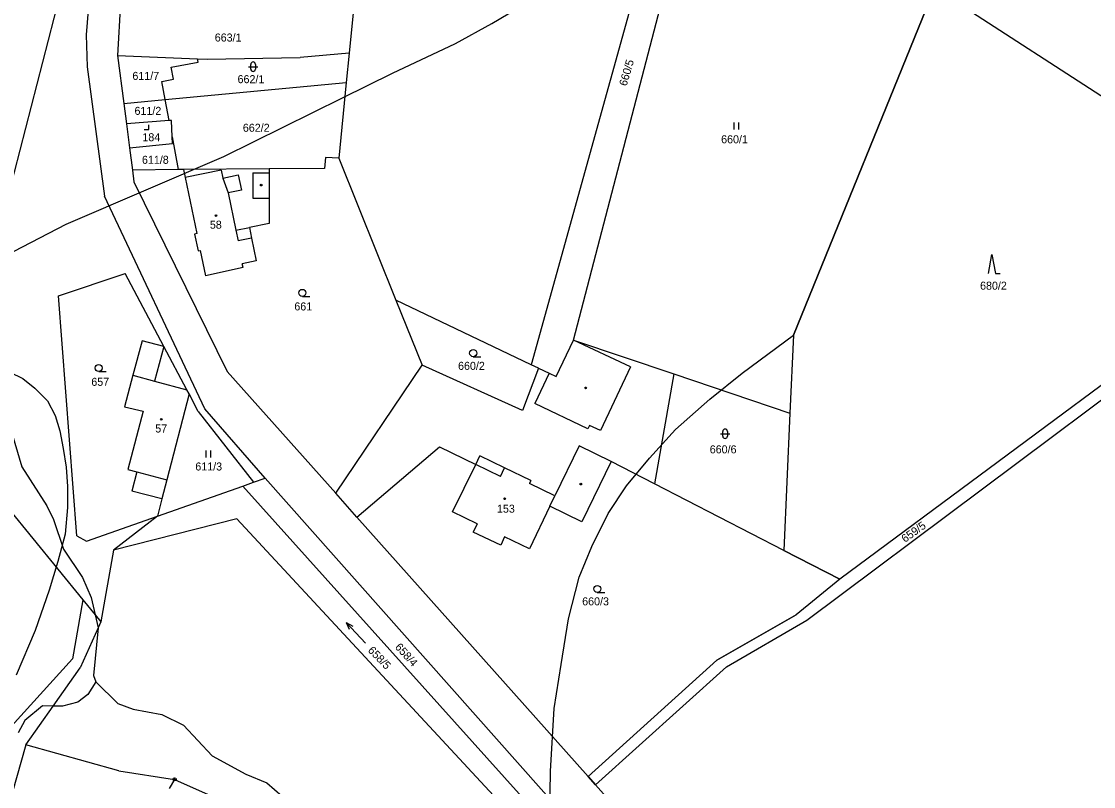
# Model space of a CAD drawing. Extents: x -546762 to -540209, y -1046851 to -1035694.
# Drawn here: x -544180.8 to -543953, y -1042590.2 to -1042427.6 of the extents above; entities that cross this region are included whole.
import ezdxf

# ---------------------------------------------------------------- set-up
doc = ezdxf.new("R2010")
doc.units = 0
for name, color, linetype in [('Vrstva 1', 7, 'Continuous'), ('Vrstva 18', 7, 'Continuous'), ('Vrstva 19', 7, 'Continuous'), ('Vrstva 24', 7, 'Continuous'), ('Vrstva 25', 7, 'Continuous'), ('Vrstva 3', 7, 'Continuous'), ('Vrstva 37', 7, 'Continuous'), ('Vrstva 4', 7, 'Continuous'), ('Vrstva 52', 7, 'Continuous')]:
    doc.layers.add(name, color=color, linetype=linetype)

msp = doc.modelspace()

# ---------------------------------------------------------------- linework, layer by layer
at = {"layer": 'Vrstva 1'}
msp.add_line((-543914, -1042467.7), (-543986.75, -1042420.55), dxfattribs=at)
for points in [[(-544038.85, -1042379.66), (-544072.43, -1042500.56)], [(-544063.47, -1042495.3), (-544034.28, -1042383.4)], [(-544164.15, -1042395.46), (-544167.03, -1042430.46)], [(-544107.72, -1042399.99), (-544111.16, -1042434.37)], [(-544169.04, -1042408.16), (-544185.97, -1042473.64)], [(-544016.72, -1042494.3), (-543986.75, -1042420.55)], [(-544159.71, -1042423.65), (-544160.33, -1042434.89)], [(-544167.03, -1042430.46), (-544166.81, -1042437.26)], [(-544160.33, -1042434.89), (-544143.34, -1042435.58)], [(-544160.33, -1042434.89), (-544159.01, -1042445.05)], [(-544148.97, -1042437.33), (-544143.21, -1042436.27)], [(-544143.34, -1042435.58), (-544141.33, -1042435.66)], [(-544143.21, -1042436.27), (-544143.34, -1042435.58)], [(-544141.33, -1042435.66), (-544121.51, -1042435.3)], [(-544111.16, -1042434.37), (-544121.51, -1042435.3)], [(-544111.16, -1042434.37), (-544111.76, -1042440.57)], [(-544166.81, -1042437.26), (-544163.09, -1042464.73)], [(-544148.49, -1042439.92), (-544148.97, -1042437.33)], [(-544150.91, -1042440.37), (-544148.49, -1042439.92)], [(-544150.2, -1042444.21), (-544150.91, -1042440.37)], [(-544150.2, -1042444.21), (-544111.76, -1042440.57)], [(-544111.76, -1042440.57), (-544113.33, -1042456.67)], [(-544159.01, -1042445.05), (-544150.2, -1042444.21)], [(-544159.01, -1042445.05), (-544158.45, -1042449.39)], [(-544149.38, -1042448.68), (-544150.2, -1042444.21)], [(-544149.38, -1042448.68), (-544158.45, -1042449.39)], [(-544158.45, -1042449.39), (-544157.79, -1042454.48)], [(-544148.9, -1042448.64), (-544149.38, -1042448.68)], [(-544148.73, -1042452.17), (-544148.9, -1042448.64)], [(-544148.66, -1042453.58), (-544148.73, -1042452.17)], [(-544148.73, -1042452.17), (-544147.44, -1042459.11)], [(-544157.79, -1042454.48), (-544148.66, -1042453.58)], [(-544157.79, -1042454.48), (-544157.18, -1042459.2)], [(-544116.18, -1042456.56), (-544116.37, -1042458.83)], [(-544113.33, -1042456.67), (-544116.18, -1042456.56)], [(-544113.33, -1042456.67), (-544101.21, -1042486.85)], [(-544147.44, -1042459.11), (-544157.18, -1042459.2)], [(-544146.34, -1042459.1), (-544147.44, -1042459.11)], [(-544128.11, -1042458.94), (-544146.34, -1042459.1)], [(-544146.34, -1042459.1), (-544145.99, -1042460.8)], [(-544128.11, -1042458.94), (-544128.12, -1042459.8)], [(-544116.37, -1042458.83), (-544128.11, -1042458.94)], [(-544157.18, -1042459.2), (-544156.86, -1042461.7)], [(-544145.99, -1042460.8), (-544143.52, -1042472.69)], [(-544128.12, -1042459.8), (-544128.13, -1042465.15)], [(-544156.86, -1042461.7), (-544137.04, -1042501.98)], [(-544141.77, -1042509.92), (-544163.09, -1042464.73)], [(-544128.13, -1042465.15), (-544128.16, -1042470.53)], [(-544128.16, -1042470.53), (-544132.34, -1042471.39)], [(-544143.52, -1042472.69), (-544143.96, -1042472.79)], [(-544143.96, -1042472.79), (-544143.23, -1042476.36)], [(-544132.34, -1042471.39), (-544131.87, -1042473.64)], [(-544131.87, -1042473.64), (-544130.88, -1042478.49)], [(-544143.23, -1042476.36), (-544142.8, -1042476.29)], [(-544142.8, -1042476.29), (-544141.65, -1042481.64)], [(-544130.88, -1042478.49), (-544133.85, -1042479.1)], [(-544133.68, -1042479.87), (-544133.85, -1042479.1)], [(-544172.9, -1042485.9), (-544158.73, -1042481.16)], [(-544150.51, -1042496.7), (-544158.73, -1042481.16)], [(-544133.68, -1042479.87), (-544141.65, -1042481.64)], [(-544169, -1042536.88), (-544172.9, -1042485.9)], [(-544101.21, -1042486.85), (-544095.65, -1042500.68)], [(-544072.43, -1042500.56), (-544101.21, -1042486.85)], [(-544155.14, -1042495.45), (-544157.11, -1042502.79)], [(-544150.51, -1042496.7), (-544155.14, -1042495.45)], [(-544067.15, -1042503.08), (-544063.47, -1042495.3)], [(-544063.47, -1042495.3), (-544042.15, -1042502.5)], [(-544016.72, -1042494.3), (-544017.46, -1042510.83)], [(-544145.65, -1042505.87), (-544150.51, -1042496.7)], [(-543939.58, -1042496.26), (-544006.86, -1042546.1)], [(-544013.86, -1042554.81), (-543939.22, -1042499.03)], [(-544113.99, -1042527.84), (-544137.04, -1042501.98)], [(-544113.99, -1042527.84), (-544095.65, -1042500.68)], [(-544074.29, -1042510.25), (-544095.65, -1042500.68)], [(-544070.87, -1042501.31), (-544074.29, -1042510.25)], [(-544070.87, -1042501.31), (-544072.43, -1042500.56)], [(-544070.87, -1042501.31), (-544068.64, -1042502.37)], [(-544068.64, -1042502.37), (-544067.15, -1042503.08)], [(-544157.11, -1042502.79), (-544158.87, -1042509.49)], [(-544042.15, -1042502.5), (-544046.28, -1042525.83)], [(-544042.15, -1042502.5), (-544017.46, -1042510.83)], [(-544145.11, -1042506.77), (-544149.87, -1042524.97)], [(-544145.11, -1042506.77), (-544145.65, -1042505.87)], [(-544143.21, -1042510.47), (-544145.11, -1042506.77)], [(-544158.87, -1042509.49), (-544154.9, -1042510.41)], [(-544154.9, -1042510.41), (-544158.13, -1042522.84)], [(-544143.21, -1042510.47), (-544131.43, -1042525.51)], [(-544128.99, -1042524.65), (-544141.77, -1042509.92)], [(-544017.46, -1042510.83), (-544018.75, -1042539.99)], [(-544109.47, -1042532.91), (-544091.91, -1042518.02)], [(-544091.91, -1042518.02), (-544084.22, -1042521.74)], [(-544158.13, -1042522.84), (-544156.25, -1042523.32)], [(-544089.17, -1042531.78), (-544084.22, -1042521.74)], [(-544055.43, -1042521.13), (-544061.66, -1042533.93)], [(-544046.28, -1042525.83), (-544055.43, -1042521.13)], [(-544156.25, -1042523.32), (-544157.31, -1042527.4)], [(-544149.87, -1042524.97), (-544150.92, -1042529.06)], [(-544131.43, -1042525.51), (-544128.99, -1042524.65)], [(-544055.22, -1042607.7), (-544128.99, -1042524.65)], [(-544150.92, -1042529.06), (-544157.31, -1042527.4)], [(-544151.86, -1042532.7), (-544133.73, -1042526.32)], [(-544133.73, -1042526.32), (-544131.43, -1042525.51)], [(-544133.73, -1042526.32), (-544057.53, -1042611.21)], [(-544018.75, -1042539.99), (-544046.28, -1042525.83)], [(-544150.92, -1042529.06), (-544151.86, -1042532.7)], [(-544109.47, -1042532.91), (-544113.99, -1042527.84)], [(-544183.66, -1042530.96), (-544167.74, -1042550.47)], [(-544083.92, -1042534.32), (-544089.17, -1042531.78)], [(-544068.48, -1042530.61), (-544072.84, -1042539.65)], [(-544061.66, -1042533.93), (-544068.48, -1042530.61)], [(-544166.94, -1042538), (-544151.86, -1042532.7)], [(-544151.86, -1042532.7), (-544161.24, -1042539.94)], [(-544135.03, -1042533.32), (-544161.24, -1042539.94)], [(-544064.09, -1042609.7), (-544135.03, -1042533.32)], [(-544060.37, -1042588.02), (-544109.47, -1042532.91)], [(-544083.92, -1042534.32), (-544084.75, -1042536.12)], [(-544078.92, -1042538.91), (-544084.75, -1042536.12)], [(-544169, -1042536.88), (-544166.94, -1042538)], [(-544078.09, -1042537.11), (-544078.92, -1042538.91)], [(-544072.84, -1042539.65), (-544078.09, -1042537.11)], [(-544161.24, -1042539.94), (-544163.9, -1042555.17)], [(-544006.86, -1042546.1), (-544018.75, -1042539.99)], [(-544006.86, -1042546.1), (-544016.14, -1042553.71)], [(-544167.74, -1042550.47), (-544169.9, -1042563.04)], [(-544167.74, -1042550.47), (-544165.08, -1042553.72)], [(-544165.08, -1042553.72), (-544163.9, -1042555.17)], [(-544032.97, -1042563.33), (-544016.14, -1042553.71)], [(-544030.98, -1042564.71), (-544013.86, -1042554.81)], [(-544164.47, -1042556.43), (-544168.31, -1042564.91)], [(-544163.9, -1042555.17), (-544164.47, -1042556.43)], [(-544185.03, -1042579.7), (-544169.9, -1042563.04)], [(-544032.97, -1042563.33), (-544060.37, -1042588.02)], [(-544174.05, -1042573.07), (-544168.31, -1042564.91)], [(-544030.98, -1042564.71), (-544058.8, -1042589.78)], [(-544179.83, -1042581.29), (-544174.05, -1042573.07)], [(-544179.83, -1042581.29), (-544188.45, -1042611.64)], [(-544160.08, -1042586.86), (-544179.83, -1042581.29)], [(-544160.08, -1042586.86), (-544148.22, -1042588.65)], [(-544148.22, -1042588.65), (-544149.36, -1042590.55)], [(-544148.22, -1042588.65), (-544135.96, -1042594.1)], [(-544058.8, -1042589.78), (-544060.37, -1042588.02)], [(-543992.15, -1042664.59), (-544058.8, -1042589.78)]]:
    msp.add_lwpolyline(points, dxfattribs=at)
at = {"layer": 'Vrstva 24'}
for radius in [0.335, 0.067]:
    msp.add_circle((-544148.22, -1042588.65), radius, dxfattribs=at)
at = {"layer": 'Vrstva 25'}
for p, q in [((-544132.55, -1042437.24), (-544130.55, -1042437.24)), ((-544132.05, -1042437.74), (-544132.05, -1042436.74)), ((-544131.05, -1042436.74), (-544131.05, -1042437.74)), ((-544029.35, -1042450.59), (-544029.35, -1042449.09)), ((-544028.35, -1042450.59), (-544028.35, -1042449.09)), ((-544121.08, -1042486.04), (-544119.48, -1042486.04)), ((-544084.78, -1042498.84), (-544083.18, -1042498.84)), ((-544164.35, -1042501.99), (-544162.75, -1042501.99)), ((-544032.26, -1042515.22), (-544030.26, -1042515.22)), ((-544031.76, -1042515.72), (-544031.76, -1042514.72)), ((-544030.76, -1042514.72), (-544030.76, -1042515.72)), ((-544141.52, -1042520.28), (-544141.52, -1042518.78)), ((-544140.52, -1042520.28), (-544140.52, -1042518.78)), ((-544058.41, -1042548.93), (-544056.81, -1042548.93))]:
    msp.add_line(p, q, dxfattribs=at)
for points in [[(-544154.7, -1042450.58), (-544153.7, -1042450.58), (-544153.7, -1042449.58)], [(-543975.28, -1042481.14), (-543974.58, -1042477.14), (-543973.78, -1042481.14), (-543972.78, -1042481.14)], [(-544107.64, -1042559.67), (-544111.78, -1042555.33), (-544111.11, -1042556.76)], [(-544111.78, -1042555.33), (-544110.38, -1042556.07)]]:
    msp.add_lwpolyline(points, dxfattribs=at)
for centre, radius in [((-544129.82, -1042462.4), 0.175), ((-544139.42, -1042468.86), 0.175), ((-544121.08, -1042485.29), 0.75), ((-544084.78, -1042498.09), 0.75), ((-544164.35, -1042501.24), 0.75), ((-544060.89, -1042505.47), 0.175), ((-544151.06, -1042512.14), 0.175), ((-544061.91, -1042525.91), 0.175), ((-544078.1, -1042529.03), 0.175), ((-544058.41, -1042548.18), 0.75)]:
    msp.add_circle(centre, radius, dxfattribs=at)
for centre, start, end in [((-544131.55, -1042436.74), 0, 180), ((-544131.55, -1042437.74), 180, 0), ((-544031.26, -1042514.72), 0, 180), ((-544031.26, -1042515.72), 180, 0)]:
    msp.add_arc(centre, 0.5, start, end, dxfattribs=at)
at = {"layer": 'Vrstva 3'}
for points in [[(-544138.34, -1042459.2), (-544145.99, -1042460.8)], [(-544145.99, -1042460.8), (-544143.52, -1042472.69)], [(-544138.34, -1042459.2), (-544137.98, -1042460.91)], [(-544137.98, -1042460.91), (-544136.82, -1042464.04)], [(-544136.82, -1042464.04), (-544135.18, -1042471.97)], [(-544143.52, -1042472.69), (-544143.96, -1042472.79)], [(-544143.96, -1042472.79), (-544143.23, -1042476.36)], [(-544135.18, -1042471.97), (-544134.71, -1042474.22)], [(-544131.87, -1042473.64), (-544134.71, -1042474.22)], [(-544131.87, -1042473.64), (-544130.88, -1042478.49)], [(-544143.23, -1042476.36), (-544142.8, -1042476.29)], [(-544142.8, -1042476.29), (-544141.65, -1042481.64)], [(-544130.88, -1042478.49), (-544133.85, -1042479.1)], [(-544133.68, -1042479.87), (-544133.85, -1042479.1)], [(-544133.68, -1042479.87), (-544141.65, -1042481.64)], [(-544157.11, -1042502.79), (-544158.87, -1042509.49)], [(-544157.11, -1042502.79), (-544152.48, -1042504.03)], [(-544152.48, -1042504.03), (-544145.65, -1042505.87)], [(-544145.11, -1042506.77), (-544149.87, -1042524.97)], [(-544145.11, -1042506.77), (-544145.65, -1042505.87)], [(-544158.87, -1042509.49), (-544154.9, -1042510.41)], [(-544154.9, -1042510.41), (-544158.13, -1042522.84)], [(-544158.13, -1042522.84), (-544156.25, -1042523.32)], [(-544089.17, -1042531.78), (-544084.22, -1042521.74)], [(-544078.97, -1042524.28), (-544084.22, -1042521.74)], [(-544078.97, -1042524.28), (-544078.13, -1042522.47)], [(-544072.52, -1042525.17), (-544078.13, -1042522.47)], [(-544156.25, -1042523.32), (-544149.87, -1042524.97)], [(-544072.52, -1042525.17), (-544072.82, -1042525.79)], [(-544067.42, -1042528.42), (-544072.82, -1042525.79)], [(-544068.48, -1042530.61), (-544067.42, -1042528.42)], [(-544083.92, -1042534.32), (-544089.17, -1042531.78)], [(-544068.48, -1042530.61), (-544072.84, -1042539.65)], [(-544083.92, -1042534.32), (-544084.75, -1042536.12)], [(-544078.92, -1042538.91), (-544084.75, -1042536.12)], [(-544078.09, -1042537.11), (-544078.92, -1042538.91)], [(-544072.84, -1042539.65), (-544078.09, -1042537.11)]]:
    msp.add_lwpolyline(points, dxfattribs=at)
at = {"layer": 'Vrstva 37'}
for centre in [(-544139.42, -1042468.86), (-544151.06, -1042512.14), (-544078.1, -1042529.03)]:
    msp.add_circle(centre, 0.175, dxfattribs=at)
at = {"layer": 'Vrstva 4'}
for points in [[(-544138.34, -1042459.2), (-544145.99, -1042460.8)], [(-544138.34, -1042459.2), (-544137.98, -1042460.91)], [(-544137.98, -1042460.91), (-544134.7, -1042460.23)], [(-544137.98, -1042460.91), (-544136.82, -1042464.04)], [(-544134.7, -1042460.23), (-544134.03, -1042463.46)], [(-544131.62, -1042459.79), (-544131.63, -1042465.14)], [(-544131.62, -1042459.79), (-544128.12, -1042459.8)], [(-544134.03, -1042463.46), (-544136.82, -1042464.04)], [(-544136.82, -1042464.04), (-544135.18, -1042471.97)], [(-544131.63, -1042465.14), (-544128.13, -1042465.15)], [(-544135.18, -1042471.97), (-544132.34, -1042471.39)], [(-544135.18, -1042471.97), (-544134.71, -1042474.22)], [(-544131.87, -1042473.64), (-544134.71, -1042474.22)], [(-544051.35, -1042501.03), (-544063.47, -1042495.3)], [(-544150.51, -1042496.7), (-544152.48, -1042504.03)], [(-544068.64, -1042502.37), (-544071.67, -1042508.77)], [(-544051.35, -1042501.03), (-544057.74, -1042514.54)], [(-544157.11, -1042502.79), (-544152.48, -1042504.03)], [(-544152.48, -1042504.03), (-544145.65, -1042505.87)], [(-544060.43, -1042514.16), (-544071.67, -1042508.77)], [(-544060.08, -1042513.43), (-544060.43, -1042514.16)], [(-544057.74, -1042514.54), (-544060.08, -1042513.43)], [(-544183.1, -1042514.08), (-544180.67, -1042522.21)], [(-544062.26, -1042517.81), (-544067.42, -1042528.42)], [(-544055.43, -1042521.13), (-544062.26, -1042517.81)], [(-544084.22, -1042521.74), (-544083.39, -1042519.94)], [(-544078.13, -1042522.47), (-544083.39, -1042519.94)], [(-544180.67, -1042522.21), (-544175.39, -1042530.5)], [(-544078.97, -1042524.28), (-544084.22, -1042521.74)], [(-544078.97, -1042524.28), (-544078.13, -1042522.47)], [(-544072.52, -1042525.17), (-544078.13, -1042522.47)], [(-544156.25, -1042523.32), (-544149.87, -1042524.97)], [(-544072.52, -1042525.17), (-544072.82, -1042525.79)], [(-544067.42, -1042528.42), (-544072.82, -1042525.79)], [(-544068.48, -1042530.61), (-544067.42, -1042528.42)], [(-544175.39, -1042530.5), (-544173.94, -1042533.4)], [(-544173.94, -1042533.4), (-544171.82, -1042539.71)], [(-544171.82, -1042539.71), (-544167.78, -1042545.77)], [(-544167.78, -1042545.77), (-544165.92, -1042550.02)], [(-544165.92, -1042550.02), (-544165.08, -1042553.72)], [(-544165.08, -1042553.72), (-544164.47, -1042556.43)], [(-544164.47, -1042556.43), (-544165.45, -1042566.54)], [(-544164.98, -1042567.94), (-544166.65, -1042570.58)], [(-544165.45, -1042566.54), (-544164.98, -1042567.94)], [(-544164.98, -1042567.94), (-544160.32, -1042572.49)], [(-544166.65, -1042570.58), (-544168.76, -1042572.21)], [(-544176.26, -1042573.05), (-544180.04, -1042576.12)], [(-544174.05, -1042573.07), (-544176.26, -1042573.05)], [(-544168.76, -1042572.21), (-544172.03, -1042573.09)], [(-544160.32, -1042572.49), (-544157.01, -1042573.74)], [(-544172.03, -1042573.09), (-544174.05, -1042573.07)], [(-544157.01, -1042573.74), (-544150.95, -1042574.87)], [(-544150.95, -1042574.87), (-544146.3, -1042577.15)], [(-544180.04, -1042576.12), (-544181.44, -1042578.75)], [(-544146.3, -1042577.15), (-544140.24, -1042583.62)], [(-544140.24, -1042583.62), (-544133.1, -1042587.5)], [(-544133.1, -1042587.5), (-544128.65, -1042589.37)], [(-544128.65, -1042589.37), (-544122.12, -1042595.06)]]:
    msp.add_lwpolyline(points, dxfattribs=at)
at = {"layer": 'Vrstva 52'}
for points in [[(-543986.21, -1042322.51), (-544008.72, -1042307.15), (-544025.54, -1042326.58), (-544012.94, -1042341.62), (-543995.73, -1042365.92), (-543978.69, -1042376.44), (-543968.12, -1042382.96), (-544001.39, -1042406.57), (-544001.11, -1042410.51), (-543986.75, -1042420.55), (-544016.72, -1042494.3)], [(-544357.18, -1042542.23), (-544333.87, -1042541.38), (-544314.37, -1042539.69), (-544298.47, -1042536.93), (-544281.94, -1042531.63), (-544265.2, -1042524.21), (-544252.43, -1042517.58), (-544215.98, -1042493.83), (-544171.26, -1042470.72), (-544137.77, -1042456.3), (-544112.54, -1042443.82), (-544101.89, -1042438.61), (-544088.56, -1042432.31), (-544080.81, -1042428.07), (-544072.34, -1042422.98)], [(-544069.01, -1042628.06), (-544068.38, -1042586.93), (-544067.56, -1042573.57), (-544066.11, -1042564.24), (-544064.53, -1042554.54), (-544062.23, -1042545.7), (-544059.57, -1042539.15), (-544056.06, -1042532.13), (-544052.18, -1042526.31), (-544047.34, -1042520.37), (-544041.77, -1042514.31), (-544034.5, -1042507.89), (-544027.6, -1042502.32), (-544016.72, -1042494.3)], [(-544016.72, -1042494.3), (-544017.46, -1042510.83)], [(-544183.24, -1042502.15), (-544180.47, -1042503.46), (-544177.91, -1042505.54), (-544175.21, -1042508.24), (-544173.62, -1042511.36), (-544172.58, -1042514.61), (-544171.89, -1042518.35), (-544171.27, -1042522.3), (-544170.99, -1042526.45), (-544170.97, -1042530.85), (-544171.46, -1042536.54), (-544173.03, -1042542.36), (-544174.85, -1042548.42), (-544177.88, -1042557.02), (-544181.87, -1042566.47)], [(-544017.46, -1042510.83), (-544018.75, -1042539.99), (-544006.86, -1042546.1), (-544016.14, -1042553.71), (-544032.97, -1042563.33), (-544060.37, -1042588.02), (-544058.8, -1042589.78), (-543996.4, -1042659.82), (-544001.87, -1042667.74), (-544007.21, -1042675.58), (-544023.53, -1042699.54), (-544007.6, -1042722.34), (-543994.35, -1042740.08), (-543978.53, -1042755.27), (-543969.68, -1042767.22), (-543967.35, -1042770.36), (-543961.17, -1042789.27), (-543956.03, -1042811.37), (-543954.4, -1042831.58), (-543959.26, -1042856.2), (-543982.29, -1042852.21), (-544009.18, -1042839.83), (-544057.02, -1042836.26), (-544068.37, -1042835.41)]]:
    msp.add_lwpolyline(points, dxfattribs=at)

# ---------------------------------------------------------------- texts
at = {"layer": 'Vrstva 18'}
for s, p in [('663/1', (-544139.69, -1042431.89)), ('611/7', (-544157.19, -1042440.04)), ('662/1', (-544134.84, -1042440.74)), ('611/2', (-544156.74, -1042447.47)), ('662/2', (-544133.72, -1042451.06)), ('660/1', (-544032.09, -1042453.51)), ('611/8', (-544155.16, -1042457.87)), ('680/2', (-543977.07, -1042484.61)), ('661', (-544122.78, -1042489.02)), ('660/2', (-544087.99, -1042501.64)), ('657', (-544165.92, -1042505.03)), ('660/6', (-544034.51, -1042519.38)), ('611/3', (-544143.82, -1042523.02)), ('660/3', (-544061.62, -1042551.67))]:
    msp.add_text(s, height=1.7, dxfattribs=at).set_placement(p)
for s, rotation, p in [('660/5', 73.7159, (-544052.18, -1042441.47)), ('659/5', 35.8334, (-543993.01, -1042538.42)), ('658/5', 314.2147, (-544107.28, -1042561.36)), ('658/4', 312.4595, (-544101.51, -1042560.64))]:
    msp.add_text(s, height=1.7, rotation=rotation, dxfattribs=at).set_placement(p)
at = {"layer": 'Vrstva 19'}
for s, p in [('184', (-544155.07, -1042453.07)), ('58', (-544140.73, -1042471.65)), ('57', (-544152.33, -1042514.95)), ('153', (-544079.72, -1042531.98))]:
    msp.add_text(s, height=1.7, dxfattribs=at).set_placement(p)

doc.saveas('drawing.dxf')
